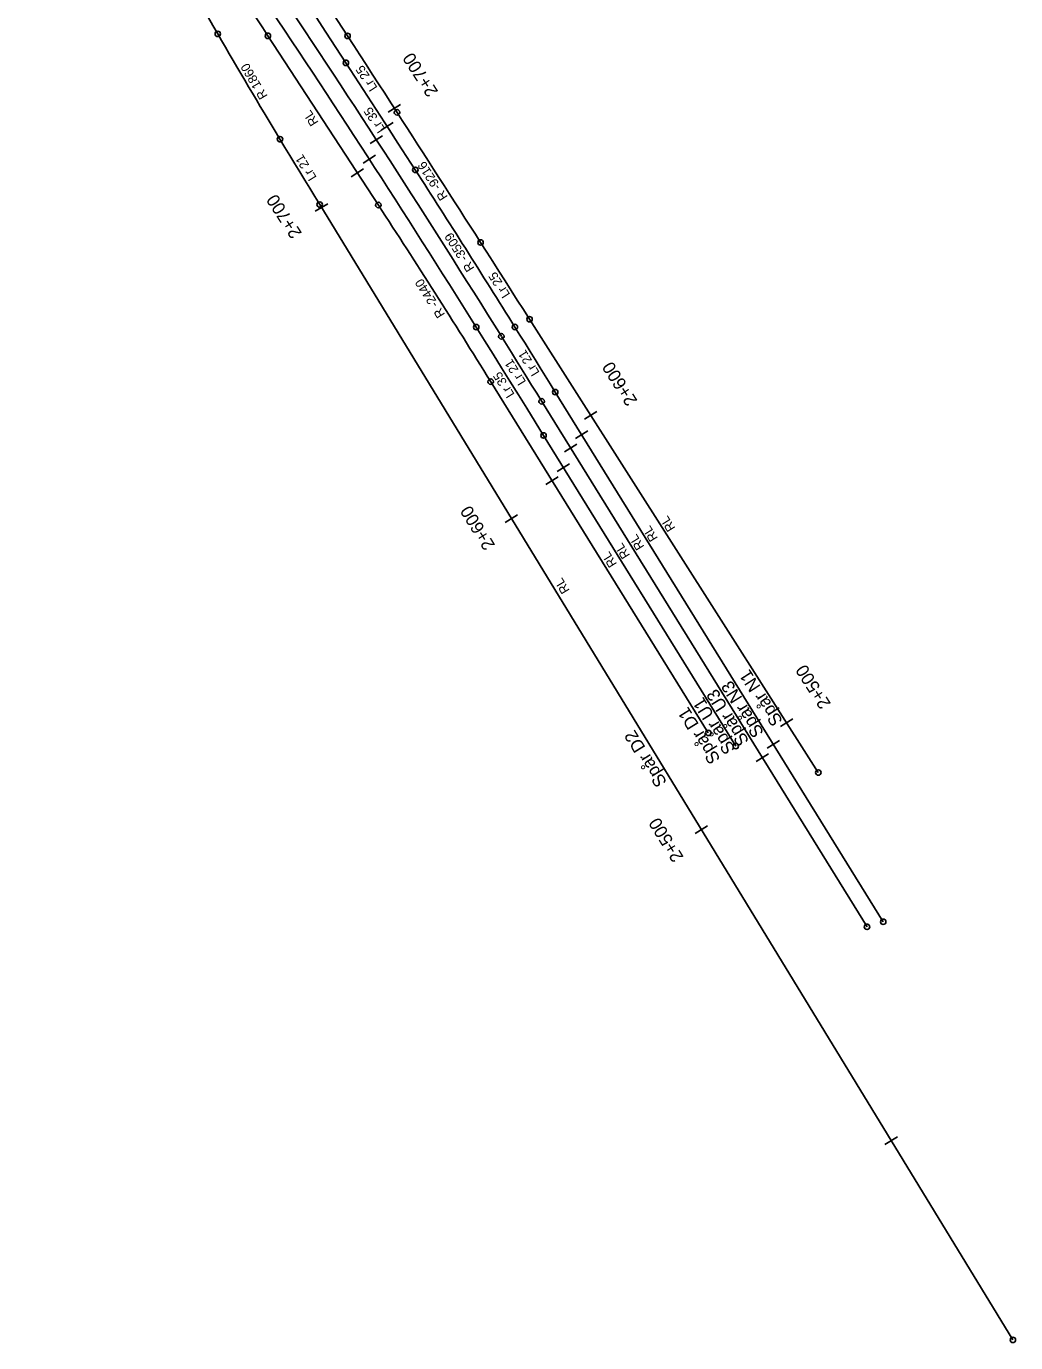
# Model space of a CAD drawing. Extents: x 149855 to 151460, y 6580726 to 6583068.
# Drawn here: x 151189 to 151460.4, y 6580725.5 to 6581086.8 of the extents above; entities that cross this region are included whole.
import ezdxf

# ---------------------------------------------------------------- set-up
doc = ezdxf.new("R2010")
doc.units = 0
for name, color, linetype in [('Hektometer L', 7, 'Continuous'), ('Hektometer T', 7, 'Continuous'), ('Spår nr T', 7, 'Continuous'), ('Spårgeometri T', 7, 'Continuous'), ('Spårmitt L', 7, 'Continuous'), ('Tp bef behålls P', 7, 'Continuous')]:
    doc.layers.add(name, color=color, linetype=linetype)

msp = doc.modelspace()

# ---------------------------------------------------------------- linework, layer by layer
at = {"layer": 'Hektometer L'}
for points in [[(151288.31, 6581063.21), (151291.67, 6581065.37)], [(151286.32, 6581058.25), (151289.68, 6581060.43)], [(151283.32, 6581054.6), (151286.68, 6581056.78)], [(151281.42, 6581049.24), (151284.78, 6581051.41)], [(151278.14, 6581045.51), (151281.49, 6581047.69)], [(151268.28, 6581036.03), (151271.69, 6581038.11)], [(151342.17, 6580978.96), (151345.54, 6580981.11)], [(151339.63, 6580973.7), (151343.03, 6580975.8)], [(151336.61, 6580970.03), (151340.01, 6580972.14)], [(151334.66, 6580964.64), (151338.06, 6580966.74)], [(151331.55, 6580961.02), (151334.95, 6580963.13)], [(151320.38, 6580950.67), (151323.79, 6580952.76)], [(151395.89, 6580894.62), (151399.26, 6580896.77)], [(151392.27, 6580888.67), (151395.67, 6580890.78)], [(151389.25, 6580885.01), (151392.65, 6580887.11)], [(151372.48, 6580865.32), (151375.89, 6580867.4)], [(151424.58, 6580779.96), (151427.99, 6580782.05)]]:
    msp.add_lwpolyline(points, dxfattribs=at)
at = {"layer": 'Spårmitt L'}
msp.add_line((151330.4, 6580983.87), (151419.65, 6580839.68), dxfattribs=at)
for points in [[(151277.13, 6581084.17), (151274.42, 6581088.37), (151271.7, 6581092.57), (151268.99, 6581096.77), (151266.27, 6581100.97), (151263.56, 6581105.17), (151260.86, 6581109.37), (151258.15, 6581113.58), (151255.45, 6581117.79), (151252.76, 6581122), (151250.07, 6581126.21), (151247.39, 6581130.43), (151244.71, 6581134.66), (151242.04, 6581138.89), (151239.38, 6581143.12)], [(151276.68, 6581076.77), (151273.95, 6581080.96), (151271.22, 6581085.15), (151268.5, 6581089.34), (151265.77, 6581093.54), (151263.05, 6581097.73), (151260.34, 6581101.93), (151257.62, 6581106.13), (151254.91, 6581110.33), (151252.21, 6581114.54), (151249.51, 6581118.74), (151246.82, 6581122.96), (151244.13, 6581127.17), (151241.45, 6581131.4), (151238.78, 6581135.62)], [(151241.52, 6581084.71), (151240.21, 6581086.99), (151238.9, 6581089.26), (151237.59, 6581091.54), (151236.29, 6581093.82), (151234.98, 6581096.09), (151233.68, 6581098.37), (151232.38, 6581100.65), (151231.08, 6581102.93)], [(151285.59, 6581037.74), (151255.29, 6581084.18)], [(151290.71, 6581063.18), (151289.01, 6581065.8), (151287.32, 6581068.43), (151285.62, 6581071.05), (151283.92, 6581073.68), (151282.23, 6581076.3), (151280.53, 6581078.92), (151278.83, 6581081.55), (151277.13, 6581084.17)], [(151295.72, 6581047.4), (151293.35, 6581051.08), (151290.97, 6581054.75), (151288.59, 6581058.43), (151286.21, 6581062.1), (151283.83, 6581065.77), (151281.45, 6581069.43), (151279.06, 6581073.1), (151276.68, 6581076.77)], [(151269.5, 6581037.87), (151268.13, 6581040.11), (151266.76, 6581042.35), (151265.39, 6581044.59), (151264.03, 6581046.83), (151262.67, 6581049.08), (151261.3, 6581051.32), (151259.95, 6581053.57), (151258.59, 6581055.81)], [(151459.68, 6580726.3), (151269.5, 6581037.87)], [(151327.06, 6581006.4), (151325.39, 6581009.04), (151323.71, 6581011.67), (151322.03, 6581014.31), (151320.35, 6581016.94), (151318.67, 6581019.58), (151316.99, 6581022.21), (151315.31, 6581024.85), (151313.63, 6581027.48)], [(151330.9, 6580974.52), (151328.6, 6580978.24), (151326.3, 6580981.96), (151323.99, 6580985.68), (151321.69, 6580989.4), (151319.38, 6580993.11), (151317.07, 6580996.83), (151314.75, 6581000.54), (151312.43, 6581004.25)], [(151334.11, 6580986.41), (151332.73, 6580988.64), (151331.35, 6580990.88), (151329.97, 6580993.11), (151328.58, 6580995.34), (151327.2, 6580997.57), (151325.82, 6580999.8), (151324.43, 6581002.03), (151323.04, 6581004.26)], [(151406.29, 6580882.01), (151327.06, 6581006.4)], [(151330.4, 6580983.87), (151329.02, 6580986.1), (151327.63, 6580988.33), (151326.25, 6580990.56), (151324.87, 6580992.79), (151323.49, 6580995.02), (151322.1, 6580997.25), (151320.71, 6580999.48), (151319.33, 6581001.71)], [(151376.11, 6580892.88), (151316.41, 6580989.27)], [(151424.1, 6580841.06), (151334.11, 6580986.41)], [(151383.65, 6580889.26), (151330.9, 6580974.52)], [(151459.68, 6580726.3), (151459.68, 6580726.3)]]:
    msp.add_lwpolyline(points, dxfattribs=at)
for centre, radius, start, end in [((148345.13, 6579148.16), 3504.5, 31.93168, 35.65829), ((148345.36, 6579147.78), 3500, 32.03381, 35.662), ((149580.27, 6579991.34), 2000, 33.12146, 34.32399), ((152851.64, 6582015.91), 1860, 210.04269, 211.07662), ((143546.99, 6576066.23), 9216, 32.570031, 32.833754), ((148345.03, 6579148.31), 3509, 31.93192, 32.76582), ((149242.06, 6579704.48), 2440, 31.77277, 33.12146)]:
    msp.add_arc(centre, radius, start, end, dxfattribs=at)
at = {"layer": 'Tp bef behålls P'}
for centre in [(151241.52, 6581084.71), (151255.29, 6581084.18), (151277.14, 6581084.16), (151276.68, 6581076.77), (151290.71, 6581063.17), (151258.59, 6581055.81), (151295.72, 6581047.4), (151269.5, 6581037.87), (151285.59, 6581037.74), (151313.63, 6581027.48), (151312.43, 6581004.25), (151323.04, 6581004.26), (151327.06, 6581006.4), (151319.33, 6581001.71), (151316.41, 6580989.27), (151334.11, 6580986.41), (151330.4, 6580983.87), (151330.9, 6580974.52), (151376.11, 6580892.88), (151383.65, 6580889.26), (151406.29, 6580882.01), (151424.1, 6580841.06), (151419.65, 6580839.68), (151459.68, 6580726.3)]:
    msp.add_circle(centre, 0.75, dxfattribs=at)

# ---------------------------------------------------------------- texts
at = {"layer": 'Hektometer T'}
for s, rotation, p in [('2+700', 122.8418, (151302.1, 6581068.88)), ('2+700', 122.928, (151264.73, 6581030.02)), ('2+600', 122.4923, (151356.78, 6580984.04)), ('2+600', 121.7473, (151317.72, 6580944.42)), ('2+500', 122.4923, (151409.85, 6580900.89)), ('2+500', 121.76, (151369.44, 6580858.81))]:
    msp.add_text(s, height=3.5, rotation=rotation, dxfattribs=at).set_placement(p)
at = {"layer": 'Spår nr T'}
for s, rotation, p in [('Spår N1', 122.9736, (151396.67, 6580896.18)), ('Spår N3', 122.0035, (151391.48, 6580892.96)), ('Spår U3', 121.8167, (151387.41, 6580890.65)), ('Spår D1', 121.8167, (151379.54, 6580885.71)), ('Spår U1', 121.8167, (151383.68, 6580888.38)), ('Spår D2', 121.8167, (151364.88, 6580879.37))]:
    msp.add_text(s, height=3.5, rotation=rotation, dxfattribs=at).set_placement(p)
at = {"layer": 'Spårgeometri T'}
for s, rotation, p in [('R 1860', 120.5597, (151255.29, 6581067.65)), ('Lr 25', 122.8856, (151285.43, 6581069.96)), ('RL', 122.9563, (151269.25, 6581060.44)), ('Lr 35', 122.9563, (151287.64, 6581058.52)), ('Lr 21', 121.2922, (151268.74, 6581045.34)), ('R -9216', 122.7019, (151304.73, 6581039.99)), ('R -3509', 122.3489, (151312.04, 6581020.4)), ('Lr 25', 122.5182, (151321.83, 6581013.22)), ('R -2440', 122.4471, (151303.97, 6581007.74)), ('Lr 21', 121.8176, (151329.91, 6580991.78)), ('Lr 21', 121.8172, (151326.19, 6580989.24)), ('Lr 35', 121.8428, (151323.04, 6580985.79)), ('RL', 121.8176, (151367.15, 6580949.08)), ('RL', 121.8176, (151358.63, 6580944)), ('RL', 121.8176, (151362.35, 6580946.34)), ('RL', 121.8176, (151351.13, 6580939.25)), ('RL', 121.8176, (151354.7, 6580941.61)), ('RL', 121.2922, (151338.16, 6580932))]:
    msp.add_text(s, height=2.5, rotation=rotation, dxfattribs=at).set_placement(p)

doc.saveas('drawing.dxf')
